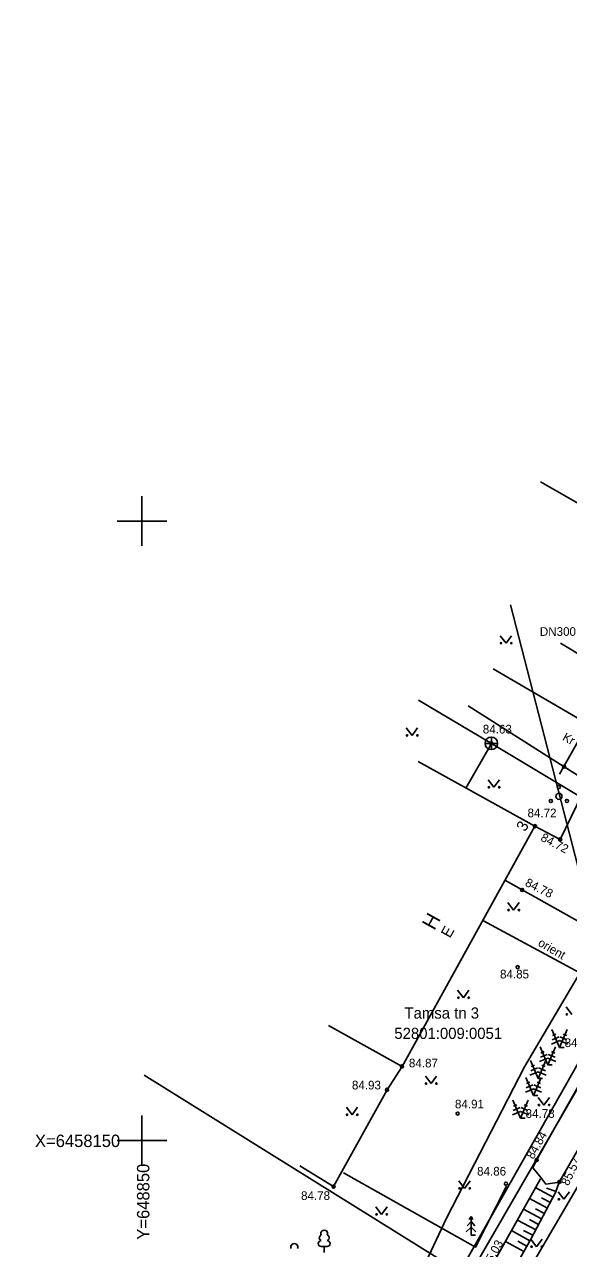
# Model space of a CAD drawing. Extents: x 648748 to 649126, y 6457789 to 6458252.
# Drawn here: x 648840.5 to 648884.4, y 6458141.3 to 6458240.1 of the extents above; entities that cross this region are included whole.
import ezdxf

# ---------------------------------------------------------------- set-up
doc = ezdxf.new("R2010")
doc.units = 0
for name, color, linetype in [('AED', 7, 'Continuous'), ('HALJASTUS', 7, 'Continuous'), ('HOONE', 7, 'Continuous'), ('KKAEV', 7, 'Continuous'), ('KORGUS-EH2000', 7, 'Continuous'), ('KTRASS', 7, 'Continuous'), ('MPKAABEL', 7, 'Continuous'), ('MPOHULIIN', 7, 'Continuous'), ('PIIR', 7, 'Continuous'), ('PUU', 7, 'Continuous'), ('RELJEEF', 7, 'Continuous'), ('SITRASS', 7, 'Continuous'), ('TEE', 7, 'Continuous'), ('TRUUP', 7, 'Continuous'), ('VEEKOGU', 7, 'Continuous'), ('VORK', 7, 'Continuous')]:
    doc.layers.add(name, color=color, linetype=linetype)

msp = doc.modelspace()

# ---------------------------------------------------------------- linework, layer by layer
at = {"layer": 'AED'}
for points in [[(648883.709, 6458179.555), (648886.185, 6458183.944), (648888.119, 6458187.534), (648883.783, 6458190.14)], [(648870.994, 6458155.974), (648869.786, 6458154.09), (648865.466, 6458146.262), (648862.749, 6458147.956)]]:
    msp.add_lwpolyline(points, dxfattribs=at)
at = {"layer": 'HALJASTUS'}
for p, q in [((648878.924, 6458190.743), (648879.387, 6458190.137)), ((648879.387, 6458190.137), (648879.833, 6458190.743)), ((648871.338, 6458183.298), (648871.802, 6458182.691)), ((648871.802, 6458182.691), (648872.247, 6458183.298)), ((648877.946, 6458179.11), (648878.41, 6458178.503)), ((648878.41, 6458178.503), (648878.855, 6458179.11)), ((648879.529, 6458169.198), (648879.992, 6458168.591)), ((648879.992, 6458168.591), (648880.438, 6458169.198)), ((648875.48, 6458162.124), (648875.944, 6458161.518)), ((648875.944, 6458161.518), (648876.389, 6458162.124)), ((648884.229, 6458160.775), (648884.692, 6458160.168)), ((648872.874, 6458155.191), (648873.338, 6458154.584)), ((648873.338, 6458154.584), (648873.783, 6458155.191)), ((648881.973, 6458153.459), (648882.437, 6458152.853)), ((648882.437, 6458152.853), (648882.882, 6458153.459)), ((648866.499, 6458152.678), (648866.962, 6458152.071)), ((648866.962, 6458152.071), (648867.408, 6458152.678)), ((648875.573, 6458146.721), (648876.037, 6458146.115)), ((648876.037, 6458146.115), (648876.482, 6458146.721)), ((648883.595, 6458145.85), (648884.058, 6458145.243)), ((648884.058, 6458145.243), (648884.504, 6458145.85)), ((648868.872, 6458144.627), (648869.336, 6458144.021)), ((648869.336, 6458144.021), (648869.781, 6458144.627)), ((648881.383, 6458142.017), (648881.847, 6458141.41)), ((648881.847, 6458141.41), (648882.292, 6458142.017))]:
    msp.add_line(p, q, dxfattribs=at)
msp.add_lwpolyline([(648866.265, 6458147.374), (648876.927, 6458141.39), (648879.421, 6458146.293)], dxfattribs=at)
for centre in [(648878.986, 6458190.137), (648879.815, 6458190.137), (648871.401, 6458182.691), (648872.23, 6458182.691), (648878.009, 6458178.503), (648878.838, 6458178.503), (648879.591, 6458168.591), (648880.42, 6458168.591), (648875.543, 6458161.518), (648876.372, 6458161.518), (648884.291, 6458160.168), (648872.937, 6458154.584), (648873.766, 6458154.584), (648866.561, 6458152.071), (648867.39, 6458152.071), (648882.036, 6458152.853), (648882.865, 6458152.853), (648875.636, 6458146.115), (648876.465, 6458146.115), (648883.657, 6458145.243), (648868.935, 6458144.021), (648869.764, 6458144.021), (648881.446, 6458141.41), (648882.275, 6458141.41)]:
    msp.add_circle(centre, 0.055, dxfattribs=at)
at = {"layer": 'HOONE'}
msp.add_lwpolyline([(648865.05, 6458159.261), (648870.994, 6458155.974), (648881.716, 6458175.368), (648872.283, 6458180.583)], dxfattribs=at)
at = {"layer": 'KKAEV'}
for p, q in [((648877.699, 6458182.051), (648878.699, 6458182.051)), ((648878.199, 6458181.551), (648878.199, 6458182.551))]:
    msp.add_line(p, q, dxfattribs=at)
msp.add_circle((648878.199, 6458182.051), 0.5, dxfattribs=at)
at = {"layer": 'KORGUS-EH2000'}
for centre in [(648878.199, 6458182.051), (648884.077, 6458180.168), (648881.716, 6458175.368), (648883.753, 6458174.295), (648880.68, 6458170.217), (648880.323, 6458163.984), (648870.994, 6458155.974), (648869.786, 6458154.09), (648875.484, 6458152.163), (648881.852, 6458148.408), (648865.466, 6458146.262), (648879.381, 6458146.496), (648883.683, 6458146.633)]:
    msp.add_circle(centre, 0.125, dxfattribs=at)
at = {"layer": 'KTRASS'}
for p, q in [((648878.199, 6458182.051), (648872.328, 6458185.545)), ((648878.199, 6458182.051), (648876.151, 6458178.445)), ((648918.483, 6458157.779), (648878.199, 6458182.051))]:
    msp.add_line(p, q, dxfattribs=at)
at = {"layer": 'MPKAABEL'}
msp.add_line((648877.501, 6458167.744), (648887.329, 6458162.432), dxfattribs=at)
at = {"layer": 'MPOHULIIN'}
msp.add_lwpolyline([(648879.733, 6458193.241), (648887.677, 6458162.414), (648896.676, 6458127.492), (648901.112, 6458110.279), (648910.288, 6458074.678)], dxfattribs=at)
at = {"layer": 'PIIR'}
for p, q in [((648882.169, 6458203.173), (648904.5, 6458190.31)), ((648904.5, 6458190.31), (648875.65, 6458139.39)), ((648875.65, 6458139.39), (648850.168, 6458155.262))]:
    msp.add_line(p, q, dxfattribs=at)
at = {"layer": 'PUU'}
for p, q in [((648883.709, 6458157.508), (648883.088, 6458158.955)), ((648883.709, 6458157.508), (648884.33, 6458158.955)), ((648883.709, 6458158.052), (648883.052, 6458157.771)), ((648883.669, 6458158.362), (648883.118, 6458158.125)), ((648883.413, 6458158.578), (648883.138, 6458158.46)), ((648883.709, 6458158.052), (648884.365, 6458157.771)), ((648883.748, 6458158.362), (648884.3, 6458158.125)), ((648884.005, 6458158.578), (648884.28, 6458158.46)), ((648882.754, 6458156.09), (648882.133, 6458157.537)), ((648882.715, 6458156.944), (648882.163, 6458156.707)), ((648882.458, 6458157.16), (648882.182, 6458157.042)), ((648882.754, 6458156.09), (648883.375, 6458157.537)), ((648882.794, 6458156.944), (648883.345, 6458156.707)), ((648883.05, 6458157.16), (648883.326, 6458157.042)), ((648884.069, 6458157.508), (648883.709, 6458157.508)), ((648881.973, 6458155.001), (648881.352, 6458156.448)), ((648881.677, 6458156.071), (648881.402, 6458155.953)), ((648881.973, 6458155.001), (648882.594, 6458156.448)), ((648882.754, 6458156.634), (648882.098, 6458156.353)), ((648882.269, 6458156.071), (648882.545, 6458155.953)), ((648882.754, 6458156.634), (648883.41, 6458156.353)), ((648883.114, 6458156.09), (648882.754, 6458156.09)), ((648881.599, 6458153.626), (648880.978, 6458155.073)), ((648881.973, 6458155.545), (648881.317, 6458155.264)), ((648881.934, 6458155.855), (648881.382, 6458155.618)), ((648881.599, 6458153.626), (648882.22, 6458155.073)), ((648881.973, 6458155.545), (648882.63, 6458155.264)), ((648882.333, 6458155.001), (648881.973, 6458155.001)), ((648882.013, 6458155.855), (648882.564, 6458155.618)), ((648881.599, 6458154.17), (648880.943, 6458153.889)), ((648881.559, 6458154.48), (648881.008, 6458154.243)), ((648881.303, 6458154.696), (648881.027, 6458154.578)), ((648881.599, 6458154.17), (648882.255, 6458153.889)), ((648881.639, 6458154.48), (648882.19, 6458154.243)), ((648881.895, 6458154.696), (648882.171, 6458154.578)), ((648880.559, 6458151.795), (648879.938, 6458153.242)), ((648880.559, 6458151.795), (648881.18, 6458153.242)), ((648881.959, 6458153.626), (648881.599, 6458153.626)), ((648880.559, 6458152.339), (648879.902, 6458152.058)), ((648880.519, 6458152.649), (648879.968, 6458152.412)), ((648880.263, 6458152.865), (648879.988, 6458152.747)), ((648880.559, 6458152.339), (648881.215, 6458152.058)), ((648880.599, 6458152.649), (648881.15, 6458152.412)), ((648880.855, 6458152.865), (648881.13, 6458152.747)), ((648880.919, 6458151.795), (648880.559, 6458151.795)), ((648876.56, 6458143.455), (648876.26, 6458143.105)), ((648876.56, 6458143.855), (648876.41, 6458143.605)), ((648876.71, 6458143.605), (648876.56, 6458143.855)), ((648876.56, 6458143.855), (648876.56, 6458142.355)), ((648876.86, 6458143.105), (648876.56, 6458143.455)), ((648876.56, 6458143.005), (648876.16, 6458142.605)), ((648876.96, 6458142.605), (648876.56, 6458143.005)), ((648876.92, 6458142.355), (648876.56, 6458142.355)), ((648864.95, 6458141.427), (648864.47, 6458141.427)), ((648864.71, 6458140.952), (648864.71, 6458141.427))]:
    msp.add_line(p, q, dxfattribs=at)
for centre, radius in [((648883.649, 6458178.522), 0.125), ((648883.649, 6458177.772), 0.25), ((648882.999, 6458177.397), 0.125), ((648884.299, 6458177.397), 0.125)]:
    msp.add_circle(centre, radius, dxfattribs=at)
for centre, radius, start, end in [((648864.54, 6458142.125), 0.233, 109.022, 253.142), ((648864.71, 6458142.472), 0.277, 332.58, 207.42), ((648864.88, 6458142.125), 0.233, 286.851, 70.986), ((648862.299, 6458141.396), 0.277, 332.58, 207.42), ((648864.472, 6458141.665), 0.238, 90.002, 269.395), ((648864.947, 6458141.665), 0.238, 270.605, 89.998)]:
    msp.add_arc(centre, radius, start, end, dxfattribs=at)
at = {"layer": 'RELJEEF'}
for p, q in [((648881.78, 6458146.177), (648883.197, 6458145.42)), ((648882.659, 6458146.129), (648883.419, 6458145.867)), ((648881.29, 6458145.305), (648882.725, 6458144.538)), ((648882.248, 6458145.36), (648882.961, 6458144.979)), ((648880.801, 6458144.433), (648882.254, 6458143.656)), ((648881.767, 6458144.483), (648882.489, 6458144.097)), ((648880.311, 6458143.561), (648881.782, 6458142.774)), ((648881.287, 6458143.606), (648882.018, 6458143.215)), ((648879.838, 6458142.719), (648881.308, 6458141.894)), ((648880.806, 6458142.729), (648881.547, 6458142.333)), ((648879.348, 6458141.848), (648880.819, 6458141.022)), ((648880.328, 6458141.871), (648881.063, 6458141.458))]:
    msp.add_line(p, q, dxfattribs=at)
for points in [[(648843.02, 6458077.359), (648843.42, 6458078.532), (648845.59, 6458084.371), (648850.065, 6458093.899), (648854.008, 6458102.777), (648855.882, 6458106.866), (648857.274, 6458110.27), (648859.944, 6458115.461), (648864.155, 6458122.302), (648866.203, 6458125.31), (648868.207, 6458128.087), (648874.51, 6458135.307), (648877.92, 6458139.306), (648882.178, 6458146.884)], [(648844.206, 6458076.8), (648844.687, 6458077.74), (648847.597, 6458083.411), (648851.411, 6458092.995), (648855.57, 6458101.941), (648857.624, 6458105.762), (648858.713, 6458108.175), (648859.587, 6458110.038), (648862.771, 6458115.697), (648866.339, 6458121.712), (648870.456, 6458126.824), (648876.009, 6458134.263), (648879.482, 6458138.641), (648881.386, 6458142.032), (648883.388, 6458145.778), (648883.683, 6458146.633)]]:
    msp.add_lwpolyline(points, dxfattribs=at)
at = {"layer": 'SITRASS'}
for points in [[(648929.925, 6458240.085), (648929.233, 6458238.833), (648926.729, 6458233.327), (648923.21, 6458225.506), (648918.966, 6458215.361), (648917.027, 6458210.342), (648911.341, 6458199.533), (648902.157, 6458183.584), (648896.992, 6458174.764), (648890.118, 6458163.377), (648888.523, 6458160), (648880.878, 6458146.779), (648876.372, 6458138.998), (648873.186, 6458136.533), (648872.398, 6458135.159), (648870.194, 6458131.921), (648868.778, 6458129.583), (648863.975, 6458121.708)], [(648896.343, 6458186.017), (648897.439, 6458185.494), (648891.994, 6458176.157), (648887.134, 6458166.562), (648880.865, 6458155.928), (648874.577, 6458143.726), (648870.442, 6458134.893), (648860.973, 6458120.207), (648854.483, 6458107.787), (648851.762, 6458098.853), (648850.917, 6458095.378), (648847.878, 6458090.581), (648844.467, 6458087.013), (648842.522, 6458085.072), (648840.521, 6458082.239)]]:
    msp.add_lwpolyline(points, dxfattribs=at)
at = {"layer": 'TEE'}
for points in [[(648878.335, 6458188.065), (648886.607, 6458183.247), (648893.979, 6458178.952), (648897.729, 6458177.041), (648900.156, 6458177.208), (648903.119, 6458178.872)], [(648881.716, 6458175.368), (648883.753, 6458174.295), (648886.01, 6458178.942), (648884.077, 6458180.168), (648876.337, 6458185.071)], [(648892.961, 6458170.34), (648889.993, 6458165.001), (648880.68, 6458170.217), (648879.296, 6458170.992)], [(648886.897, 6458149.241), (648880.501, 6458138.274), (648877.651, 6458133.428), (648873.007, 6458125.579), (648869.584, 6458119.515), (648862.268, 6458107.116), (648858.84, 6458100.574), (648853.992, 6458092.302), (648848.947, 6458082.671), (648845.759, 6458077.188), (648844.3, 6458074.59)]]:
    msp.add_lwpolyline(points, dxfattribs=at)
at = {"layer": 'VEEKOGU'}
msp.add_lwpolyline([(648894.824, 6458171.369), (648894.188, 6458170.423), (648893.695, 6458169.558), (648890.688, 6458164.197), (648885.8, 6458155.403), (648881.852, 6458148.408), (648881.551, 6458147.775), (648882.109, 6458147.118), (648882.61, 6458146.464), (648883.683, 6458146.633), (648888.008, 6458154.101), (648892.53, 6458163.125), (648895.927, 6458168.395), (648896.425, 6458169.506), (648896.234, 6458170.624), (648896.101, 6458171.13)], dxfattribs=at)
at = {"layer": 'VORK'}
for p, q in [((648850, 6458202), (648850, 6458198)), ((648848, 6458200), (648852, 6458200)), ((648850, 6458152), (648850, 6458148)), ((648848, 6458150), (648852, 6458150))]:
    msp.add_line(p, q, dxfattribs=at)

# ---------------------------------------------------------------- texts
at = {"layer": 'HOONE'}
for s, height, p in [('3', 0.9, (648880.94, 6458174.87)), ('H', 1.2, (648873.595, 6458166.893)), ('E', 0.9, (648874.865, 6458166.27))]:
    msp.add_text(s, height=height, rotation=61.06355, dxfattribs=at).set_placement(p)
at = {"layer": 'KORGUS-EH2000'}
for s, p in [('84.63', (648877.509, 6458182.846)), ('84.72', (648881.12, 6458176.083)), ('84.85', (648878.9, 6458163.071)), ('84.76', (648884.116, 6458157.531)), ('84.87', (648871.546, 6458155.889)), ('84.93', (648866.947, 6458154.111)), ('84.91', (648875.262, 6458152.584)), ('84.78', (648880.966, 6458151.818)), ('84.86', (648877.049, 6458147.157)), ('84.78', (648862.841, 6458145.188))]:
    msp.add_text(s, height=0.7, dxfattribs=at).set_placement(p)
for s, rotation, p in [('84.72', 332.22211, (648882.115, 6458174.231)), ('84.78', 333.59107, (648880.858, 6458170.577)), ('84.84', 60.70273, (648881.589, 6458148.427)), ('85.57', 64.82431, (648884.418, 6458146.282)), ('85.03', 60.66799, (648878.046, 6458139.662))]:
    msp.add_text(s, height=0.7, rotation=rotation, dxfattribs=at).set_placement(p)
at = {"layer": 'MPKAABEL'}
msp.add_text('orient', height=0.7, rotation=329.83139, dxfattribs=at).set_placement((648881.9, 6458165.756))
at = {"layer": 'PIIR'}
for s, p in [('Tamsa tn 3', (648871.189, 6458159.83)), ('52801:009:0051', (648870.368, 6458158.19))]:
    msp.add_text(s, height=0.9, rotation=0, dxfattribs=at).set_placement(p)
at = {"layer": 'TEE'}
msp.add_text('Kr', height=0.7, rotation=330.64225, dxfattribs=at).set_placement((648883.874, 6458182.346))
at = {"layer": 'TRUUP'}
msp.add_text('DN300 asb', height=0.7, dxfattribs=at).set_placement((648882.114, 6458190.728))
at = {"layer": 'VORK'}
msp.add_text('X=6458150     ', height=1, dxfattribs=at).set_placement((648841.367, 6458149.462))
msp.add_text('Y=648850     ', height=1, rotation=90, dxfattribs=at).set_placement((648850.6, 6458141.979))

doc.saveas('drawing.dxf')
